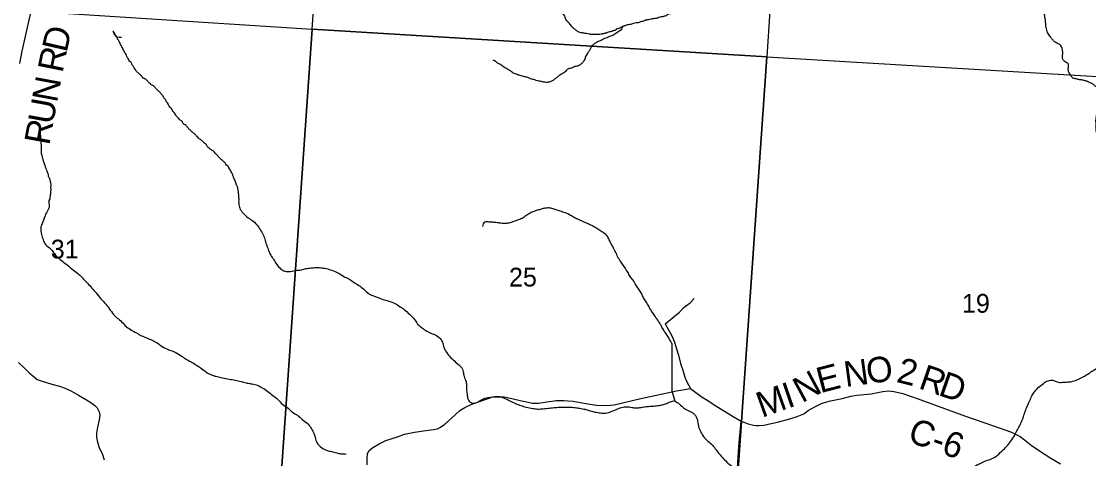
# Model space of a CAD drawing. Extents: x -13.7 to 34, y 0 to 32.3.
# Drawn here: x 26.069 to 28.447, y 15.02 to 15.995 of the extents above; entities that cross this region are included whole.
import ezdxf

# ---------------------------------------------------------------- set-up
doc = ezdxf.new("R2010")
doc.units = 0
for name, color, linetype in [('GM_X_Corporation', 7, 'Continuous'), ('GM_X_County_Road', 7, 'Continuous'), ('GM_X_County_Road_Text', 7, 'Continuous'), ('GM_X_Minor_River', 7, 'Continuous'), ('GM_X_Section_Text', 7, 'Continuous'), ('GM_X_Township_Road', 7, 'Continuous'), ('GM_X_Township_Road_Text', 7, 'Continuous')]:
    doc.layers.add(name, color=color, linetype=linetype)

msp = doc.modelspace()

# ---------------------------------------------------------------- linework, layer by layer
at = {"layer": 'GM_X_Corporation'}
for points in [[(27.2726, 16.9674), (27.7957, 16.9352), (27.7886, 16.8172), (27.7611, 16.3953), (27.73, 15.9158), (26.7165, 15.9781), (26.789, 16.9963)], [(25.6876, 16.0444), (26.7165, 15.9781), (26.6464, 14.9606), (25.6185, 15.0191)], [(26.7165, 15.9781), (27.73, 15.9158), (27.6593, 14.9006), (26.6464, 14.9606)], [(27.73, 15.9158), (28.7402, 15.8562), (28.6615, 14.8398), (27.6593, 14.9006)]]:
    msp.add_lwpolyline(points, close=True, dxfattribs=at)
at = {"layer": 'GM_X_County_Road'}
for points in [[(27.5033, 15.3211), (27.5178, 15.294), (27.5241, 15.2798), (27.5283, 15.265), (27.5332, 15.2508), (27.5374, 15.2325), (27.5422, 15.218), (27.5468, 15.2024), (27.5507, 15.1931), (27.5548, 15.1852), (27.5598, 15.1769), (27.5685, 15.1699), (27.5859, 15.1577), (27.5979, 15.1498), (27.6126, 15.1405), (27.6547, 15.1147), (27.6723, 15.1042)], [(27.6723, 15.1042), (27.688, 15.0983), (27.6997, 15.0949), (27.7058, 15.094), (27.7125, 15.094), (27.7233, 15.0951), (27.7328, 15.097), (27.7533, 15.1016), (27.7811, 15.1095), (27.7974, 15.1145), (27.8119, 15.1206), (27.8219, 15.1274), (27.8366, 15.1356), (27.8533, 15.1443), (27.8715, 15.1496), (27.8972, 15.1548), (27.9171, 15.1594), (27.9303, 15.1618), (27.9622, 15.1648), (27.9766, 15.1675), (27.9882, 15.1704), (28.0006, 15.1715), (28.0129, 15.1702), (28.0232, 15.1679), (28.0329, 15.1654), (28.0648, 15.1546), (28.1722, 15.1154), (28.2328, 15.0945), (28.275, 15.0791), (28.2938, 15.07), (28.3035, 15.062), (28.3185, 15.0508), (28.3373, 15.0375), (28.3624, 15.0217), (28.3843, 15.0092)], [(27.6941, 14.8901), (27.6888, 14.8957), (27.6723, 14.9132), (27.6649, 14.925), (27.6625, 14.9352), (27.6621, 14.9482), (27.6639, 14.9871), (27.6675, 15.0478), (27.6723, 15.1042)]]:
    msp.add_lwpolyline(points, dxfattribs=at)
at = {"layer": 'GM_X_Minor_River'}
msp.add_lwpolyline([(27.5178, 15.2768), (27.5183, 15.2321), (27.5183, 15.1717), (27.5246, 15.1484)], dxfattribs=at)
for points in [[(27.3602, 15.9665), (27.3534, 15.9659), (27.3477, 15.9658), (27.3393, 15.966), (27.3363, 15.9665), (27.3337, 15.967), (27.3272, 15.9679), (27.3227, 15.9685), (27.3189, 15.9694), (27.3159, 15.9698), (27.311, 15.9711), (27.3088, 15.9724), (27.3058, 15.9747), (27.3025, 15.9767), (27.2995, 15.9795), (27.2969, 15.9815), (27.2948, 15.9846), (27.2911, 15.9881), (27.2882, 15.992), (27.2852, 15.9948), (27.2827, 15.9987), (27.2806, 16.0026), (27.2795, 16.006), (27.2774, 16.0099), (27.2741, 16.0145), (27.2705, 16.0207), (27.2679, 16.0227), (27.2658, 16.0274), (27.2636, 16.0293), (27.2581, 16.0348), (27.2555, 16.0364), (27.2537, 16.0388), (27.2511, 16.0408), (27.2485, 16.0439), (27.2032, 16.0963), (27.2006, 16.0979), (27.1984, 16.0999), (27.1947, 16.1034), (27.1914, 16.1062), (27.1888, 16.1093), (27.1862, 16.1121), (27.1849, 16.1171), (27.1838, 16.1201), (27.1825, 16.1255), (27.1814, 16.1278), (27.18, 16.1301), (27.1775, 16.1359), (27.1725, 16.1437), (27.1072, 16.2602), (27.1047, 16.263), (27.1021, 16.2665), (27.0995, 16.2681), (27.0962, 16.2709), (27.0932, 16.2728), (27.0903, 16.2752), (27.088, 16.2761), (27.0858, 16.278), (27.0836, 16.2789), (27.0787, 16.2817), (27.0727, 16.2842), (27.0705, 16.2854), (27.0668, 16.287), (27.0634, 16.2887), (27.0612, 16.2899), (27.0585, 16.2911), (27.0559, 16.2919), (27.0537, 16.2928), (27.051, 16.294), (27.0477, 16.2956), (27.045, 16.2961), (27.0428, 16.2966), (27.0394, 16.2971), (27.0356, 16.2983), (27.0334, 16.2988), (27.0296, 16.2997), (27.0251, 16.3006), (27.0224, 16.301), (26.9299, 16.2935), (26.9265, 16.2928), (26.9242, 16.2929), (26.9185, 16.2919), (26.9139, 16.2917), (26.907, 16.29), (26.9021, 16.2891), (26.8955, 16.2866), (26.8906, 16.2856), (26.8833, 16.2829), (26.8786, 16.2803), (26.8748, 16.2793), (26.8721, 16.2783), (26.8679, 16.2769), (26.8648, 16.2762), (26.861, 16.2745), (26.8583, 16.273), (26.8529, 16.2709), (26.8506, 16.2695), (26.8478, 16.2673)], [(28.3923, 15.9068), (28.3901, 15.9092), (28.3887, 15.9122), (28.3885, 15.9179), (28.3886, 15.9202), (28.3891, 15.924), (28.3888, 15.9271), (28.3885, 15.9305), (28.3882, 15.9328), (28.3869, 15.9374), (28.3836, 15.942), (28.3806, 15.9444), (28.3776, 15.9457), (28.3735, 15.9481), (28.3706, 15.9493), (28.3687, 15.952), (28.3658, 15.9548), (28.3626, 15.9598), (28.3593, 15.9637), (28.3567, 15.968), (28.3539, 15.973), (28.3532, 15.9757), (28.3523, 15.9815), (28.3516, 15.9841), (28.3513, 15.9868), (28.3508, 15.994), (28.3505, 15.9967), (28.3498, 15.9998), (28.349, 16.0078), (28.3483, 16.012), (28.3486, 16.0188), (28.3483, 16.0215), (28.3481, 16.028), (28.3478, 16.0302), (28.3475, 16.0329), (28.3474, 16.0398), (28.3471, 16.0443), (28.3466, 16.0516), (28.3463, 16.0539), (28.3457, 16.0588), (28.3454, 16.0622), (28.3448, 16.0661), (28.3435, 16.0714), (28.3425, 16.0753), (28.3404, 16.0814), (28.3383, 16.086), (28.3358, 16.0926), (28.3344, 16.0949), (28.3337, 16.0972), (28.332, 16.1022), (28.3284, 16.1095), (28.3277, 16.1122), (28.3267, 16.1149), (28.3242, 16.1207), (28.3224, 16.1246), (28.3207, 16.1299), (28.319, 16.1338), (28.318, 16.1384), (28.3169, 16.1411), (28.3159, 16.1453), (28.3152, 16.1476), (28.3142, 16.1518), (28.3121, 16.1572), (28.3107, 16.1599), (28.3089, 16.1622), (28.3067, 16.165), (28.3022, 16.1678), (28.2974, 16.1699), (28.2925, 16.1731), (28.2895, 16.1743), (28.2866, 16.1759), (28.2795, 16.1803), (28.2754, 16.1824), (28.268, 16.1875), (28.2631, 16.1904), (28.2564, 16.1925), (28.2512, 16.1972), (28.2467, 16.1993), (28.24, 16.2033), (28.2363, 16.2049), (28.2337, 16.2065), (28.2281, 16.2098), (28.2251, 16.211), (28.2169, 16.2155), (28.2143, 16.2167), (28.212, 16.2179), (28.2072, 16.2211), (28.205, 16.2223), (28.1987, 16.2267), (28.196, 16.2275), (28.1901, 16.2319), (28.1864, 16.2339), (28.1838, 16.2352), (28.1804, 16.2372), (28.1774, 16.2396), (28.17, 16.2455), (28.1641, 16.2495)], [(27.7473, 16.1239), (27.7443, 16.1236), (27.7344, 16.1239), (27.7298, 16.1237), (27.7264, 16.1234), (27.7218, 16.1228), (27.7184, 16.1226), (27.7138, 16.1216), (27.7112, 16.1209), (27.7066, 16.1199), (27.7012, 16.1182), (27.6973, 16.116), (27.695, 16.1153), (27.6873, 16.1122), (27.6835, 16.1112), (27.68, 16.1101), (27.6731, 16.1073), (27.6701, 16.1067), (27.6674, 16.1056), (27.6627, 16.1035), (27.6593, 16.1021), (27.6558, 16.0999), (27.6531, 16.0993), (27.6508, 16.0978), (27.645, 16.0946), (27.6419, 16.0939), (27.6396, 16.0929), (27.6361, 16.0907), (27.6327, 16.0889), (27.6291, 16.086), (27.6257, 16.0846), (27.6225, 16.0809), (27.6198, 16.0795), (27.614, 16.0743), (27.6093, 16.0707), (27.6069, 16.0674), (27.6006, 16.0615), (27.5967, 16.0574), (27.594, 16.0556), (27.5909, 16.0534), (27.5842, 16.0487), (27.5808, 16.0477), (27.5746, 16.0437), (27.5719, 16.0427), (27.5696, 16.0412), (27.5645, 16.0372), (27.5614, 16.0362), (27.5591, 16.0347), (27.5537, 16.0315), (27.551, 16.0304), (27.5483, 16.029), (27.5429, 16.0258), (27.5383, 16.0244), (27.5355, 16.0218), (27.5328, 16.0208), (27.5305, 16.0197), (27.5263, 16.0172), (27.5236, 16.0162), (27.5213, 16.0151), (27.5189, 16.014), (27.5163, 16.013), (27.5128, 16.0116), (27.5093, 16.0105), (27.5051, 16.0077), (27.5012, 16.0066), (27.4978, 16.0056), (27.4913, 16.0043), (27.4867, 16.0026), (27.4829, 16.0019), (27.4802, 16.0013), (27.4745, 16.0007), (27.4687, 15.9994), (27.463, 15.9984), (27.4596, 15.9978), (27.4549, 15.9956), (27.4504, 15.9946), (27.4431, 15.9922), (27.4385, 15.9916), (27.4328, 15.9907), (27.4236, 15.9879), (27.4186, 15.9873), (27.4151, 15.9856), (27.4125, 15.9849), (27.4094, 15.9842), (27.4071, 15.9832), (27.404, 15.9814), (27.4001, 15.9792), (27.3959, 15.9782), (27.3924, 15.9757), (27.3893, 15.9746), (27.3867, 15.974), (27.3813, 15.9719), (27.3767, 15.9712), (27.3732, 15.9695), (27.3698, 15.9688), (27.3671, 15.9681), (27.3602, 15.9665)], [(27.4086, 15.9839), (27.4058, 15.9779), (27.4022, 15.9738), (27.3929, 15.9681), (27.3886, 15.9648), (27.384, 15.9626), (27.379, 15.9613), (27.374, 15.9588), (27.3682, 15.9567), (27.3625, 15.9539), (27.3582, 15.9517), (27.354, 15.9503), (27.3493, 15.9478), (27.3427, 15.9431), (27.3388, 15.9387), (27.3351, 15.9316), (27.3312, 15.9256), (27.3284, 15.9216), (27.3259, 15.9171), (27.3247, 15.9129), (27.323, 15.9088), (27.3206, 15.9047), (27.3155, 15.8999), (27.3081, 15.8956), (27.3001, 15.8936), (27.2951, 15.8911), (27.2893, 15.8898), (27.2839, 15.8869), (27.2777, 15.8807), (27.2734, 15.8782), (27.2684, 15.8753), (27.2637, 15.8716), (27.2582, 15.8673), (27.2528, 15.8633), (27.247, 15.8604), (27.2428, 15.8594), (27.2382, 15.8592), (27.2326, 15.8598), (27.225, 15.8615), (27.2186, 15.8625), (27.213, 15.8646), (27.2081, 15.8659), (27.2024, 15.8676), (27.1972, 15.8697), (27.1927, 15.871), (27.1878, 15.8719), (27.1825, 15.8736), (27.1776, 15.8749), (27.1686, 15.8782), (27.1627, 15.8814), (27.1586, 15.8846), (27.153, 15.8882), (27.1478, 15.8907), (27.1433, 15.8935), (27.1389, 15.8967), (27.1348, 15.8995), (27.1299, 15.9023), (27.1251, 15.9059), (27.1203, 15.9087)], [(26.2833, 15.9554), (26.2805, 15.9616), (26.2772, 15.967), (26.2762, 15.9694), (26.2743, 15.9717), (26.2729, 15.9744), (26.275, 15.9675), (26.2918, 15.9597)], [(26.5532, 15.6), (26.5534, 15.6072), (26.5528, 15.6106), (26.5529, 15.6129), (26.5519, 15.6198), (26.5509, 15.6232), (26.5506, 15.6255), (26.5496, 15.6278), (26.5481, 15.6305), (26.5471, 15.6332), (26.5457, 15.6378), (26.5447, 15.6417), (26.5425, 15.6455), (26.5411, 15.6486), (26.5401, 15.6513), (26.538, 15.6575), (26.5351, 15.6621), (26.5333, 15.6656), (26.5301, 15.6699), (26.5298, 15.6722), (26.526, 15.6746), (26.5232, 15.6796), (26.521, 15.6812), (26.5187, 15.6832), (26.515, 15.6863), (26.5117, 15.6895), (26.5084, 15.6926), (26.5052, 15.6973), (26.5022, 15.7001), (26.496, 15.7063), (26.4923, 15.7087), (26.4871, 15.7123), (26.4837, 15.7155), (26.4805, 15.7209), (26.4768, 15.7233), (26.4735, 15.7265), (26.4676, 15.7316), (26.4646, 15.7336), (26.4613, 15.7375), (26.4591, 15.7395), (26.4565, 15.7419), (26.451, 15.7474), (26.4488, 15.7486), (26.4444, 15.7537), (26.4422, 15.7552), (26.4403, 15.7576), (26.4356, 15.7627), (26.4311, 15.7659), (26.4286, 15.7686), (26.4264, 15.7729), (26.4242, 15.7741), (26.4216, 15.7757), (26.4161, 15.7827), (26.4132, 15.7855), (26.4107, 15.7901), (26.4066, 15.7944), (26.4038, 15.7995), (26.3998, 15.8041), (26.3965, 15.8088), (26.3958, 15.8115), (26.3925, 15.815), (26.3897, 15.8212), (26.3875, 15.8232), (26.3835, 15.8298), (26.381, 15.8325), (26.3766, 15.838), (26.3736, 15.84), (26.3711, 15.8431), (26.3685, 15.8455), (26.3645, 15.8502), (26.3615, 15.8522), (26.3563, 15.8557), (26.3526, 15.8589), (26.3504, 15.8616), (26.3449, 15.8664), (26.34, 15.8688), (26.3371, 15.8723), (26.3327, 15.877), (26.3268, 15.8822), (26.3242, 15.8849), (26.3232, 15.8872), (26.3203, 15.8919), (26.3185, 15.8942), (26.3167, 15.897), (26.3131, 15.9032), (26.3072, 15.9106), (26.3066, 15.9129), (26.3044, 15.9152), (26.3026, 15.921), (26.2994, 15.9253), (26.2972, 15.9299), (26.2951, 15.9342), (26.2926, 15.9384), (26.2908, 15.9411), (26.2887, 15.9458), (26.2869, 15.9504), (26.2833, 15.9554)], [(28.5097, 15.5993), (28.5105, 15.6019), (28.5125, 15.6053), (28.5141, 15.6083), (28.5146, 15.6105), (28.5162, 15.6135), (28.5175, 15.618), (28.5199, 15.6229), (28.5208, 15.6255), (28.522, 15.6289), (28.5233, 15.6315), (28.5242, 15.6357), (28.525, 15.6387), (28.5259, 15.6432), (28.5268, 15.6462), (28.5269, 15.6489), (28.5262, 15.6512), (28.5256, 15.655), (28.5223, 15.6604), (28.5205, 15.6628), (28.5202, 15.6651), (28.5169, 15.669), (28.514, 15.6736), (28.5104, 15.6791), (28.5086, 15.6814), (28.5053, 15.6838), (28.5009, 15.6889), (28.4987, 15.6912), (28.4965, 15.694), (28.4929, 15.7002), (28.4907, 15.7029), (28.4886, 15.7079), (28.4853, 15.7118), (28.482, 15.7165), (28.4777, 15.7223), (28.4751, 15.7247), (28.4725, 15.7274), (28.47, 15.7321), (28.4678, 15.7348), (28.466, 15.7372), (28.4654, 15.7398), (28.4645, 15.7475), (28.4638, 15.7502), (28.4635, 15.7528), (28.4633, 15.7582), (28.463, 15.7608), (28.4632, 15.7654), (28.463, 15.7726), (28.4631, 15.7764), (28.4636, 15.7798), (28.4642, 15.7851), (28.4647, 15.7877), (28.4655, 15.7904), (28.4668, 15.7938), (28.4676, 15.7968), (28.4697, 15.8024), (28.4702, 15.805), (28.471, 15.8073), (28.4715, 15.8107), (28.472, 15.8133), (28.4724, 15.8164), (28.4729, 15.8201), (28.4735, 15.8254), (28.4736, 15.8285), (28.473, 15.8338), (28.472, 15.8377), (28.4698, 15.84), (28.4677, 15.8454), (28.4655, 15.847), (28.4626, 15.8501), (28.4603, 15.8517), (28.4574, 15.8545), (28.4551, 15.8557), (28.4488, 15.8589), (28.4458, 15.8602), (28.4436, 15.8614), (28.4406, 15.8626), (28.4364, 15.8632), (28.4323, 15.8644), (28.4289, 15.8649), (28.4262, 15.865), (28.4228, 15.8659), (28.4191, 15.8672), (28.4161, 15.8676), (28.4115, 15.8689), (28.409, 15.8713), (28.4072, 15.8744), (28.405, 15.8779), (28.4025, 15.8818), (28.4014, 15.8848), (28.4017, 15.892), (28.4021, 15.8947), (28.4019, 15.8974), (28.4016, 15.8997), (28.399, 15.9024), (28.3968, 15.9036), (28.3923, 15.9068)], [(26.133, 15.5998), (26.1331, 15.6044), (26.1336, 15.607), (26.134, 15.6093), (26.1342, 15.6138), (26.1347, 15.6165), (26.1348, 15.6218), (26.1346, 15.6252), (26.1348, 15.6324), (26.1341, 15.6355), (26.1335, 15.6393), (26.1328, 15.6416), (26.1318, 15.6455), (26.1296, 15.6482), (26.1293, 15.6505), (26.128, 15.657), (26.1259, 15.6616), (26.1238, 15.667), (26.1228, 15.6701), (26.1221, 15.6735), (26.1186, 15.682), (26.1179, 15.6843), (26.1173, 15.6877), (26.1162, 15.6908), (26.1149, 15.6958), (26.1142, 15.6981), (26.1139, 15.7008), (26.1136, 15.7042), (26.1134, 15.7084), (26.1135, 15.711), (26.1133, 15.7168), (26.1134, 15.719), (26.1131, 15.7213), (26.1131, 15.7236), (26.1129, 15.7285), (26.1123, 15.7331), (26.1121, 15.7377), (26.1118, 15.7404), (26.1115, 15.7426), (26.1116, 15.7449), (26.1109, 15.7472), (26.1106, 15.7495)], [(26.133, 15.5998), (26.1303, 15.596), (26.131, 15.5831), (26.126, 15.5714), (26.121, 15.5604), (26.1148, 15.5441), (26.1121, 15.5338), (26.1139, 15.5201), (26.1172, 15.5083), (26.1229, 15.4976), (26.1342, 15.4877), (26.1451, 15.4739), (26.1579, 15.4621), (26.1707, 15.4521), (26.1851, 15.4406), (26.1964, 15.4318), (26.2073, 15.4204), (26.2186, 15.4089), (26.2284, 15.3974), (26.2374, 15.3871), (26.2491, 15.3734), (26.2593, 15.3619), (26.2694, 15.3482), (26.28, 15.3359), (26.2902, 15.3275), (26.3003, 15.3168), (26.3117, 15.3084), (26.3253, 15.3007), (26.3362, 15.2945), (26.348, 15.2895), (26.3601, 15.2845), (26.371, 15.2784), (26.3827, 15.2703), (26.396, 15.2634), (26.4077, 15.2595), (26.4228, 15.2511), (26.4338, 15.2434), (26.447, 15.2361), (26.4576, 15.2296), (26.4674, 15.2234), (26.4806, 15.2135), (26.4969, 15.2054), (26.5078, 15.2027), (26.5203, 15.1999), (26.5351, 15.1972), (26.5488, 15.1948), (26.5613, 15.1917), (26.5722, 15.189), (26.5829, 15.187), (26.595, 15.1839), (26.6056, 15.1785), (26.618, 15.1701), (26.629, 15.1613), (26.6395, 15.1528), (26.6508, 15.1417), (26.6629, 15.1329), (26.6731, 15.1237), (26.6837, 15.1172), (26.6942, 15.108), (26.7056, 15.0992), (26.7138, 15.0893), (26.7195, 15.0786), (26.7232, 15.068), (26.7273, 15.0561), (26.7375, 15.0451), (26.7499, 15.0385), (26.7602, 15.0362), (26.7715, 15.0331), (26.7814, 15.0315), (26.7924, 15.0307)], [(26.5532, 15.6), (26.5532, 15.587), (26.5566, 15.576), (26.5641, 15.5661), (26.5739, 15.5573), (26.5852, 15.55), (26.5969, 15.5374), (26.6044, 15.5252), (26.61, 15.5137), (26.6137, 15.5008), (26.6178, 15.4894), (26.6219, 15.4787), (26.6279, 15.4688), (26.6343, 15.4585), (26.6418, 15.4482), (26.6532, 15.4393), (26.6645, 15.4374), (26.679, 15.44), (26.6926, 15.4414), (26.7029, 15.444), (26.7143, 15.4454), (26.7242, 15.4465), (26.7363, 15.4461), (26.7484, 15.4441), (26.7605, 15.4402), (26.7757, 15.4337), (26.787, 15.4268), (26.798, 15.421), (26.8078, 15.4149), (26.8176, 15.4083), (26.8289, 15.4007), (26.8406, 15.39), (26.852, 15.3838), (26.8618, 15.3803), (26.8747, 15.3753), (26.8872, 15.3718), (26.9012, 15.3664), (26.9129, 15.3591), (26.9227, 15.3522), (26.9333, 15.3426), (26.9449, 15.3304), (26.9517, 15.3205), (26.9623, 15.3113), (26.9721, 15.3044), (26.9846, 15.299), (26.9967, 15.2928), (27.0057, 15.2825), (27.009, 15.2715), (27.0135, 15.2608), (27.0233, 15.2482), (27.0342, 15.2375), (27.0455, 15.2276), (27.0527, 15.2169), (27.0545, 15.2062), (27.0586, 15.1948), (27.0608, 15.1845), (27.0607, 15.1724), (27.0622, 15.1613), (27.0648, 15.151), (27.0746, 15.1441), (27.0852, 15.1464), (27.097, 15.1531), (27.1077, 15.1565), (27.121, 15.1583), (27.132, 15.159), (27.1433, 15.1559), (27.1543, 15.1509), (27.1664, 15.1447), (27.1785, 15.1397), (27.1902, 15.1362), (27.2043, 15.1331), (27.2168, 15.1311), (27.2281, 15.1314), (27.2422, 15.1329), (27.2559, 15.1343), (27.2684, 15.135), (27.2798, 15.1353), (27.2927, 15.1352), (27.3055, 15.134), (27.3158, 15.1321), (27.3275, 15.1297), (27.3442, 15.125), (27.3563, 15.1227), (27.3681, 15.1219), (27.3795, 15.1241), (27.3992, 15.1323), (27.4129, 15.1356), (27.4262, 15.1352), (27.436, 15.1336), (27.447, 15.1343), (27.4581, 15.1361), (27.4687, 15.1372), (27.4812, 15.1379), (27.4918, 15.1394), (27.5017, 15.1416), (27.5116, 15.1457), (27.5226, 15.1494)], [(27.5178, 15.2768), (27.5114, 15.2894), (27.5054, 15.2985), (27.4986, 15.3092), (27.4934, 15.3184), (27.4885, 15.3264), (27.4814, 15.3363), (27.4757, 15.3451), (27.4705, 15.3531), (27.4652, 15.3626), (27.4592, 15.3722), (27.454, 15.3813), (27.4499, 15.3901), (27.4435, 15.3989), (27.4378, 15.4076), (27.4315, 15.4183), (27.4251, 15.4267), (27.4198, 15.4359), (27.4131, 15.4466), (27.4067, 15.4561), (27.3995, 15.4668), (27.3883, 15.4897), (27.3838, 15.4977), (27.3797, 15.5057), (27.3752, 15.5152), (27.3661, 15.5236), (27.3575, 15.529), (27.3488, 15.5348), (27.3397, 15.5398), (27.3318, 15.5436), (27.32, 15.549), (27.3083, 15.554), (27.2988, 15.5586), (27.2902, 15.564), (27.2743, 15.5702), (27.2648, 15.5736), (27.2557, 15.5764), (27.2459, 15.5791), (27.2371, 15.5788), (27.2292, 15.5773), (27.2212, 15.5747), (27.2124, 15.5721), (27.2045, 15.5691), (27.1949, 15.5634), (27.1866, 15.5574), (27.1767, 15.5529), (27.1679, 15.5499), (27.1569, 15.5458), (27.1482, 15.5447), (27.1368, 15.5452), (27.1262, 15.5467), (27.1178, 15.5475), (27.1091, 15.548), (27.1011, 15.5476), (27.0958, 15.5378)], [(27.5226, 15.1494), (27.5325, 15.144), (27.5426, 15.1352), (27.5528, 15.1283), (27.5649, 15.1222), (27.574, 15.11), (27.5765, 15.0967), (27.5795, 15.086), (27.5855, 15.0742), (27.5957, 15.0616), (27.6062, 15.0528), (27.6149, 15.0424), (27.6228, 15.0321), (27.6333, 15.0199), (27.6431, 15.0107), (27.6541, 15.0012), (27.6639, 14.9924), (27.674, 14.9828), (27.6842, 14.9721), (27.6951, 14.9614), (27.7064, 14.9484), (27.7159, 14.9381), (27.7256, 14.9262), (27.7354, 14.9163), (27.7445, 14.906), (27.7543, 14.8964), (27.7667, 14.8865), (27.7765, 14.878), (27.789, 14.87), (27.8007, 14.8619), (27.8105, 14.8562), (27.8223, 14.85), (27.8362, 14.8431), (27.8461, 14.8392), (27.8567, 14.8357), (27.8817, 14.8295), (27.8927, 14.8287), (27.9033, 14.8305), (27.914, 14.8373), (27.9239, 14.8456), (27.9365, 14.8569), (27.9483, 14.8705), (27.9575, 14.8804), (27.9671, 14.8913), (27.9774, 14.9038), (27.9896, 14.9117), (28.0037, 14.9185), (28.0166, 14.923), (28.0303, 14.9267), (28.0432, 14.9308), (28.0554, 14.9353), (28.0706, 14.9413), (28.0808, 14.9465), (28.0915, 14.9506), (28.1048, 14.9566), (28.1155, 14.9611), (28.1303, 14.9687), (28.141, 14.9728), (28.1528, 14.9799), (28.1627, 14.9863), (28.1733, 14.9923), (28.1863, 14.9995), (28.1977, 15.0063), (28.2076, 15.0111), (28.2175, 15.0156), (28.2319, 15.0205), (28.243, 15.0277), (28.2563, 15.0401), (28.2663, 15.0503), (28.2755, 15.0624), (28.2839, 15.0764), (28.2897, 15.0878), (28.295, 15.098), (28.3004, 15.1109), (28.3047, 15.1238), (28.3089, 15.1352), (28.3136, 15.1454), (28.3189, 15.1576), (28.3247, 15.1674), (28.3457, 15.1882), (28.3564, 15.1942), (28.3666, 15.1953), (28.3768, 15.1914), (28.3886, 15.1906), (28.4003, 15.1913), (28.4117, 15.1931), (28.4228, 15.1972), (28.4342, 15.2025), (28.4468, 15.2104), (28.4567, 15.2168), (28.4681, 15.2239), (28.4784, 15.2281), (28.4882, 15.228), (28.4988, 15.2264), (28.5091, 15.226), (28.5189, 15.224), (28.5671, 15.2287)]]:
    msp.add_spline(points, degree=3, dxfattribs=at)
at = {"layer": 'GM_X_Township_Road'}
for points in [[(26.0896, 16.0181), (26.0697, 15.9286), (26.0643, 15.9014)], [(27.5033, 15.3211), (27.5352, 15.3467), (27.5437, 15.3566), (27.5482, 15.3606), (27.5591, 15.3677), (27.5676, 15.3771)], [(26.0622, 15.2344), (26.077, 15.2204), (26.0866, 15.2109), (26.0943, 15.205), (26.1042, 15.1971), (26.115, 15.193), (26.1367, 15.1861), (26.1541, 15.1821), (26.1663, 15.1776), (26.1807, 15.1707), (26.1957, 15.1622), (26.214, 15.1516), (26.2239, 15.1453), (26.2321, 15.139), (26.2375, 15.1334), (26.242, 15.1244), (26.2434, 15.1173), (26.2424, 15.1068), (26.2381, 15.0903), (26.2361, 15.0772), (26.2361, 15.068), (26.2381, 15.0571), (26.242, 15.0449), (26.2493, 15.0297), (26.253, 15.0177)], [(26.8391, 15.0063), (26.8394, 15.0221), (26.8396, 15.0315), (26.843, 15.038), (26.8516, 15.0452), (26.866, 15.0531), (26.8811, 15.0607), (26.907, 15.0691), (26.9226, 15.0747), (26.9446, 15.0794), (26.9696, 15.083), (26.9868, 15.0854), (26.9957, 15.0871), (27.0027, 15.0906), (27.012, 15.097), (27.035, 15.1179), (27.0458, 15.1275), (27.0566, 15.1343), (27.0723, 15.142), (27.109, 15.1544), (27.1187, 15.1581), (27.1305, 15.1585), (27.1444, 15.1579), (27.1614, 15.1546), (27.1833, 15.1496), (27.1978, 15.1463), (27.2075, 15.1442), (27.2208, 15.1438), (27.2398, 15.1471), (27.2608, 15.15), (27.2765, 15.15), (27.298, 15.1482), (27.3266, 15.1434), (27.35, 15.1397), (27.3734, 15.1386), (27.3892, 15.1407), (27.449, 15.1544), (27.501, 15.1658), (27.5285, 15.1718), (27.5598, 15.1769)]]:
    msp.add_lwpolyline(points, dxfattribs=at)

# ---------------------------------------------------------------- texts
at = {"layer": 'GM_X_County_Road_Text'}
for s, height, rotation, p in [('N', 0.0568, 7.669, (27.9051, 15.18)), ('O', 0.0568, 8.0057, (27.955, 15.1868)), ('2', 0.0568, 345.9764, (28.0162, 15.1918)), ('E', 0.0568, 14.5778, (27.8486, 15.1661)), ('R', 0.0568, 340.8159, (28.0654, 15.178)), ('N', 0.0568, 28.3454, (27.808, 15.1436)), ('D', 0.0568, 340.7909, (28.1094, 15.1627)), ('M', 0.0568, 19.7063, (27.7187, 15.1112)), ('I', 0.0568, 18.9681, (27.7766, 15.132)), ('C-6', 0.05682, 340.4078, (28.0408, 15.0593))]:
    msp.add_text(s, height=height, rotation=rotation, dxfattribs=at).set_placement(p)
at = {"layer": 'GM_X_Section_Text'}
for s, p in [('31', (26.1343, 15.4666)), ('25', (27.1551, 15.4041)), ('19', (28.1643, 15.3457))]:
    msp.add_text(s, height=0.04186, rotation=0, dxfattribs=at).set_placement(p)
at = {"layer": 'GM_X_Township_Road_Text'}
for s, rotation, p in [('D', 77.0638, (26.1695, 15.924)), ('R', 78.638, (26.1604, 15.8786)), ('N', 79.5231, (26.148, 15.8125)), ('U', 79.716, (26.1391, 15.7634)), ('R', 79.7388, (26.1308, 15.7174))]:
    msp.add_text(s, height=0.0568, rotation=rotation, dxfattribs=at).set_placement(p)

doc.saveas('drawing.dxf')
